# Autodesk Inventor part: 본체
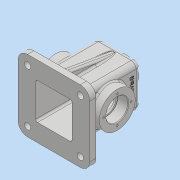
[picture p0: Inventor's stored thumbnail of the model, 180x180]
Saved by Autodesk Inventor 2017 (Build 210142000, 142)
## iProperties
Part Number: 본체
Material: 일반
Document SubType Name: Modeling
Designer: MRC
Density: 1 g/cm^3
Appearance: 기본값
Author: MRC
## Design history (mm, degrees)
sketch "스케치1"
  geometry: L1 (-34, 53)-(34, 53); L2 (34, 53)-(34, -52); L3 (34, -52)-(-34, -52); L4 (-34, -52)-(-34, 53); 2 further points
  constraints: 8 end point, 2 parallel, 1 horizontal, 1 midpoint, 1 perpendicular, 1 vertical alignment
  dimensions: "d2" = 68 distance of L2.end L3.end; "d3" = 105 distance of L1.end L2.end; "d4" = 52 distance of point (0, -52) point (0, 0)
extrude "돌출1" new body sketch "스케치1" stored distance "d5" = 68; taper "d6" = 0 deg
fillet "모깎기1" dims "d7" = 8
feature "쉘1" dims "d8" = 5
sketch "스케치2"
  geometry: C1 r 28.5 at (34, 52); 1 further point
  constraints: 1 centre point, 1 coincident
  dimensions: "d9" = 57 diameter of C1
extrude "돌출2" join sketch "스케치2" distance "d10" = 15; taper "d11" = 0 deg
sketch "스케치3"
  geometry: C1 r 28.5 at (0, 0) reference; 1 further point
  constraints: 1 coincident
hole "구멍1" sketch "스케치3" at (0, 0) diameter "d12" = 30; stored, may be unused: countersink angle "d16" = 90 deg, drill point angle "d18" = 0 deg; dims "d13" = 6, "d14" = 35, "d15" = 17, "d17" = 20
fillet "모깎기2" dims "d19" = 0.3
chamfer "모따기1" distance "d20" = 1; stored, may be unused: second distance "d21" = 2, angle "d22" = 45 deg
sketch "스케치4" dims "d23" = 44
  geometry: C1 r 18.5 at (0, 0) reference; 2 further points
  constraints: 1 coincident, 1 vertical alignment, 2 other
hole "구멍2" sketch "스케치4" at (0, 22) diameter "d24" = 3.242; stored, may be unused: countersink angle "d28" = 90 deg, drill point angle "d30" = 118 deg; dims "d25" = 8, "d26" = 35, "d27" = 17, "d29" = 10
fillet "모깎기4" dims "d35" = 0.3
chamfer "모따기2" distance "d36" = 1; stored, may be unused: second distance "d37" = 2, angle "d38" = 45 deg
sketch "스케치5"
  geometry: L1 (68, 0)-(68, -68) reference; L2 (0, 0)-(68, 0) reference; L3 (0, 0)-(0, -68) reference; L4 (68, -68)-(0, -68) reference; L5 (-23, -91)-(91, -91); L6 (91, -91)-(91, 23); L7 (91, 23)-(-23, 23); L8 (-23, 23)-(-23, -91); L9 (-23, -91)-(91, 23); L10 (91, -91)-(-23, 23); 1 further point
  constraints: 12 end point, 2 midpoint, 2 parallel, 1 horizontal, 1 perpendicular
  dimensions: "d40" = 114 distance of L7.end L6.end; "d41" = 114 distance of L6.end L5.end
extrude "돌출3" join sketch "스케치5" distance "d42" = 10; taper "d43" = 0 deg
fillet "모깎기6" dims "d44" = 15
sketch "스케치7"
  geometry: C1 r 20 at (26, -26); 1 further point
  constraints: 1 centre point, 1 coincident
  dimensions: "d47" = 40 diameter of C1
extrude "돌출4" join sketch "스케치7" distance "d48" = 10; taper "d49" = 0 deg
sketch "스케치8"
  geometry: C1 r 20 at (0, 0) reference; 1 further point
  constraints: 1 coincident
hole "구멍3" sketch "스케치8" at (0, 0) diameter "d50" = 22.835; stored, may be unused: countersink angle "d54" = 90 deg, drill point angle "d56" = 0 deg; dims "d51" = 50, "d52" = 35, "d53" = 17, "d55" = 59.3
sketch "스케치9"
  geometry: A1 r 15 centre (76, 76) between (91, 76) and (76, 91) reference; A2 r 15 centre (-8, 76) between (-8, 91) and (-23, 76) reference; A3 r 15 centre (-8, -8) between (-23, -8) and (-8, -23) reference; A4 r 15 centre (76, -8) between (76, -23) and (91, -8) reference; 5 further points
  constraints: 4 coincident
hole "구멍4" sketch "스케치9" at (76, -8), (-8, -8), (-8, 76), (76, 76) diameter "d57" = 10; stored, may be unused: countersink angle "d61" = 90 deg, drill point angle "d63" = 0 deg; dims "d58" = 50, "d59" = 18, "d60" = 2, "d62" = 59.3
sketch "스케치10"
  geometry: L1 (45, 29)-(-52, 29) reference; L2 (-52, 29)-(-52, 57) reference; L3 (-52, 57)-(-42, 57) reference; L4 (-42, 57)-(-42, 34) reference; L5 (-42, 34)-(45, 34) reference; L6 (53, 26)-(53, 20) reference; L7 (53, 20)-(63, 20) reference; L8 (63, 20)-(63, 11.418) reference; L9 (63, 11.418)-(48, 11.418) reference; L10 (48, 11.418)-(48, 26) reference; L11 (45, -34)-(-42, -34) reference; L12 (-42, -34)-(-42, -57) reference; L13 (-42, -57)-(-52, -57) reference; L14 (-52, -57)-(-52, -29) reference; L15 (-52, -29)-(45, -29) reference; L16 (48, -26)-(48, -11.418) reference; L17 (48, -11.418)-(63, -11.418) reference; L18 (63, -11.418)-(63, -20) reference; L19 (63, -20)-(53, -20) reference; L20 (53, -20)-(53, -26) reference; L21 (-6.124, 42.674)-(-42, 49); A1 r 3 centre (45, 26) between (48, 26) and (45, 29) reference; A2 r 8 centre (45, 26) between (53, 26) and (45, 34) reference; A3 r 8 centre (45, -26) between (45, -34) and (53, -26) reference; A4 r 3 centre (45, -26) between (45, -29) and (48, -26) reference; 1 further point
  constraints: 2 end point, 1 point on line
  dimensions: "d64" = 8 distance of L21.end L3.end; "d65" = 10 deg angle of L21 L3
feature "리브1" sketch "스케치10" dims "d66" = 1, "d67" = 10, "d68" = 0, "d69" = 0, "d70" = 1, "d71" = 1
fillet "모깎기7" dims "d72" = 8
fillet "모깎기8" dims "d73" = 3
fillet "모깎기9" dims "d74" = 3
fillet "모깎기10" dims "d75" = 3
fillet "모깎기11" dims "d76" = 3
fillet "모깎기12" dims "d77" = 3
fillet "모깎기13" dims "d78" = 3
sketch "스케치11"
  geometry: L1 (-8, 0)-(-8, -87) reference; L2 (46, 18)-(6, 18) reference; 1 further point
  constraints: 1 other
  dimensions: "d80" = 34 distance from line of L1 point (26, -7); "d81" = 25 distance from line of point (26, -7) L2
feature "엠보싱1" sketch "스케치11" dims "d82" = 0.5, "d83" = 0
fillet "모깎기15" dims "d84" = 3
fillet "모깎기16" dims "d85" = 3
fillet "모깎기17" dims "d86" = 3
feature "면 기울기1" dims angle "d87" = 8 deg
fillet "모깎기18" dims "d88" = 3
node "솔리드1"
pattern_circular "원형 패턴1" dims angle "d32" = 360 deg
mirror "미러1"
mirror "미러2"
node "절단 모서리 투영1"
